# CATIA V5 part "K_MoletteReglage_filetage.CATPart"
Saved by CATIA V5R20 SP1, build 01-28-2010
Part number: molette_filetage
Bounding box of the stored display mesh (mm): x -20 to 20, y 0 to 30, z -20 to 20
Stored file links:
  G:\Khaled_CFAO_2011\SIL\SIL_GR1\mroland\Khaled\CAD_CATIA_Modifie\K_MoletteReglage_filetage.CATPart
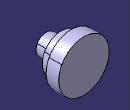
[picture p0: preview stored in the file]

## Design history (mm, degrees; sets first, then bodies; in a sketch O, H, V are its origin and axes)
Set1
  Sketch1 on xy-plane, origin (0, 0, 0), H (1, 0, 0), V (0, 1, 0)
    line L1 (0, 0) -> (0, 30)
    line L2 (0, 30) -> (20, 30)
    line L3 (20, 30) -> (20, 20)
    line L4 (20, 20) -> (15, 20)
    line L5 (15, 20) -> (15, 12)
    line L6 (15, 12) -> (8, 12)
    line L7 (8, 12) -> (8, 0)
    point P7 (8, 0)
    line L8 (8, 0) -> (0, 0)
    length L2 = 20
    length L1 = 30
    length L3 = 10
    length L4 = 5
    length L8 = 8
    length L5 = 8
    vertical: L1 V, L3 V, L5 V, L7 V
    horizontal: L2 H, L4 H, L6 H, L8 H
    coincidence: P7 H
Body1 (main body)
  Shaft1: profile Sketch1, axis Sketch1.L1, angle 360
  Sketch2 on face of Shaft1 from Sketch1.L8, origin (0, 0, 0), H (1, 0, 0), V (0, 0, 1)
    point P1 (0, 0)
  Hole1: placed by Sketch2, at (0, 0, 0) direction (0, 1, 0), diameter 10, depth 10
